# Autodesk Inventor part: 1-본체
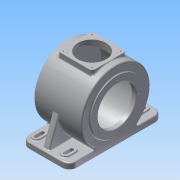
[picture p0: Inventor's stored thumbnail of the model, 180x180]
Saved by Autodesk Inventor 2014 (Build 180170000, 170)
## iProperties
Created: 2015-06
Part Number: 1-본체
Material: 알루미늄 6061
Document SubType Name: Modeling
Designer: Administrator
Density: 2.71 g/cm^3
Appearance: 알루미늄 - 평지
Mass: 3266.43 g
Surface Area: 2316.58 cm^2
Volume: 1205.33 cm^3
Author: Administrator
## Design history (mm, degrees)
sketch "스케치1"
  geometry: L1 (-67, 0)-(67, 0); L2 (-67, 0)-(-67, 65); L3 (-67, 65)-(-54, 65); L4 (-54, 65)-(-54, 85); L5 (-54, 85)-(64, 85); L6 (64, 85)-(64, 65); L7 (64, 65)-(67, 65); L8 (67, 65)-(67, 47.5); L9 (67, 47.5)-(56, 47.5); L10 (56, 47.5)-(56, 77); L11 (56, 77)-(-46, 77); L12 (-46, 77)-(-46, 31); L13 (-46, 31)-(-42.5, 29.368); L14 (-42.5, 29.368)-(-42.5, 23.5); L15 (-42.5, 23.5)-(-56.5, 23.5); L16 (-56.5, 23.5)-(-56.5, 15); L17 (-56.5, 15)-(-59.5, 15); L18 (-59.5, 15)-(-59.5, 0); 2 further points
  constraints: 36 end point, 11 parallel, 3 perpendicular, 1 coincident, 1 collinear, 1 horizontal, 1 midpoint, 1 point on line, 1 vertical, 1 vertical alignment
  dimensions: "d5" = 134 distance of L1.start L1.end; "d6" = 170 diameter of L5 L1; "d7" = 130 diameter of L3 L1; "d8" = 130 diameter of L7 L1; "d9" = 95 diameter of L9 L1; "d10" = 154 diameter of L11 L1; "d11" = 30 diameter of L17 L1; "d12" = 47 diameter of L15 L1; "d13" = 115 deg angle of L13 L12; "d14" = 62 diameter of L12.end L1; "d15" = 14 distance of L14.end L15.end; "d16" = 3 distance of L16.end L17.end; "d17" = 8 distance between parallel lines of L12 L4; "d18" = 8 distance between parallel lines of L6 L10; "d19" = 3.5 horizontal distance of L12.end L13.end; "d20" = 118 distance of L4.end L5.end; "d21" = 11 distance of L8.end L9.end
revolve "회전1" sketch "스케치1" stored, may be unused: angle "d22" = 90 deg
node "작업 평면1"
sketch "스케치2"
  geometry: L1 (46, -115)-(-36, -115); L2 (-54, -97)-(-54, 97); L3 (-36, 115)-(46, 115); L4 (64, 97)-(64, -97); L5 (64, -115)-(-54, 115); L6 (-54, -115)-(64, 115); L7 (-54, -85)-(-54, 85) reference; L8 (64, -85)-(64, 85) reference; L9 (-67, -65)-(-67, 65) reference; A1 r 18 centre (-36, -97) between (-54, -97) and (-36, -115); A2 r 18 centre (46, -97) between (46, -115) and (64, -97); A3 r 18 centre (46, 97) between (64, 97) and (46, 115); A4 r 18 centre (-36, 97) between (-36, 115) and (-54, 97); 3 further points
  constraints: 12 end point, 8 point on circle, 8 point on line, 8 tangent, 4 centre point, 4 midpoint, 3 equal radius, 2 collinear, 2 parallel, 1 horizontal, 1 horizontal alignment, 1 perpendicular
  dimensions: "d26" = 18 radius of A1; "d83" = 230 distance between parallel lines of L1 L3
extrude "돌출2" join sketch "스케치2" distance "d27" = 14; taper "d28" = 0 deg
node "작업 평면2"
sketch "스케치4"
  geometry: L1 (-37.5, 42.5)-(47.5, 42.5); L2 (47.5, 42.5)-(47.5, -42.5); L3 (47.5, -42.5)-(-37.5, -42.5); L4 (-37.5, -42.5)-(-37.5, 42.5); L5 (-37.5, 42.5)-(47.5, -42.5); L6 (47.5, 42.5)-(-37.5, -42.5); L7 (46, 115)-(-36, 115) reference; L8 (-67, -65)-(-67, 65) reference; 5 further points
  constraints: 12 end point, 6 midpoint, 2 parallel, 1 horizontal, 1 horizontal alignment, 1 perpendicular, 1 vertical, 1 vertical alignment
  dimensions: "d101" = 85 distance of L1.end L2.end
extrude "돌출3" join sketch "스케치4" stored distance "d41" = 14; taper "d42" = 0 deg
sketch "스케치7"
  geometry: L1 (64, -97)-(64, -46.733) reference; L2 (-45, -97)-(-45, -81); L3 (-27, -81)-(-27, -97); A1 r 18 centre (-36, -97) between (-54, -97) and (-36, -115) reference; A2 r 9 centre (-36, -81) between (-27, -81) and (-45, -81); A3 r 9 centre (-36, -97) between (-45, -97) and (-27, -97); 1 further point
  constraints: 4 end point, 4 point on circle, 4 tangent, 2 centre point, 2 parallel, 1 coincident
  dimensions: "d58" = 18 distance between parallel lines of L2 L3; "d59" = 16 distance of A2.centre A1.centre
extrude "돌출4" join sketch "스케치7" distance "d60" = 3; taper "d61" = 0 deg
sketch "스케치8"
  geometry: L1 (-45, -81)-(-45, -97) reference; L2 (-27, -97)-(-27, -81) reference; L3 (-40, -97)-(-40, -81); L4 (-32, -81)-(-32, -97); A1 r 9 centre (-36, -97) between (-45, -97) and (-27, -97) reference; A2 r 9 centre (-36, -81) between (-27, -81) and (-45, -81) reference; A3 r 4 centre (-36, -81) between (-32, -81) and (-40, -81); A4 r 4 centre (-36, -97) between (-40, -97) and (-32, -97); 1 further point
  constraints: 4 end point, 4 point on circle, 2 centre point, 3 other
  dimensions: "d62" = 8 distance between parallel lines of L3 L4
extrude "돌출5" cut sketch "스케치8" stored distance "d63" = 3; taper "d64" = 0 deg
sketch "스케치9"
  geometry: L1 (-97, -71)-(-115, -71) reference; L2 (115, -71)-(97, -71) reference; L3 (-109, -71)-(-84.87, -4.703); L4 (109, -71)-(84.87, -4.703); L5 (-115, -85)-(-115, -71) reference; L6 (115, -85)-(115, -71) reference; L7 (-109, -71)-(-46.733, -71); L8 (46.733, -71)-(109, -71); A1 r 85 centre (0, 0) between (-84.87, -4.703) and (84.87, -4.703) reference; 1 further point
  constraints: 8 end point, 4 point on circle, 4 point on line, 1 collinear
  dimensions: "d65" = 110 deg angle of L1 L3; "d66" = 6 distance from line of L3.start L5; "d67" = 110 deg angle of L2 L4; "d68" = 6 distance from line of L4.start L6
extrude "돌출6" join sketch "스케치9" stored distance "d69" = 15; taper "d70" = 0 deg
sketch "스케치10"
  geometry: L1 (29.799, -71)-(-29.799, -71) reference; A1 r 77 centre (0, 0) between (29.799, -71) and (-29.799, -71) reference; 2 further points
  constraints: 1 coincident, 3 other
extrude "돌출7" cut sketch "스케치10" stored distance "d71" = 102; taper "d72" = 0 deg
extrude "돌출8" cut sketch "스케치10" stored distance "d73" = 15; taper "d74" = 0 deg
sketch "스케치11"
  geometry: C1 r 65 at (0, 0) reference; C2 r 47.5 at (0, 0) reference; A1 r 55 centre (0, 0) between (-55, 0) and (0, -55); 2 further points
  constraints: 4 point on circle, 2 horizontal alignment, 2 vertical alignment, 1 centre point, 1 coincident
  dimensions: "d75" = 110 diameter of A1
hole "구멍3" sketch "스케치11" at (-55, 0), (0, -55), (0, 55), (55, 0) diameter "d76" = 3.242; stored, may be unused: countersink angle "d80" = 90 deg, drill point angle "d82" = 0 deg; dims "d77" = 10, "d78" = 4, "d79" = 2, "d81" = 13
fillet "모깎기1" dims "d84" = 3
fillet "모깎기2" dims "d85" = 3
fillet "모깎기3" dims "d86" = 3
fillet "모깎기4" dims "d87" = 3
fillet "모깎기5" dims "d88" = 3
fillet "모깎기6" dims "d89" = 3
node "작업 평면5"
  node "작업 평면4"
sketch "스케치12"
  geometry: 2 further points
  constraints: 1 coincident, 1 other
feature "엠보싱1" sketch "스케치12" dims "d5" = 134, "d92" = 1, "d93" = 0
fillet "모깎기7" dims "d94" = 3
fillet "모깎기8" dims "d95" = 0.3
fillet "모깎기9" dims "d96" = 3
chamfer "모따기1" distance "d97" = 1; stored, may be unused: second distance "d98" = 2, angle "d99" = 45 deg
fillet "모깎기10" dims "d100" = 7
sketch "스케치13"
  geometry: L1 (-30.5, 42.5)-(40.5, 42.5) reference; L2 (-30.5, -35.5)-(40.5, -35.5); L3 (40.5, -35.5)-(40.5, 35.5); L4 (40.5, 35.5)-(-30.5, 35.5); L5 (-30.5, 35.5)-(-30.5, -35.5); L6 (-30.5, -35.5)-(40.5, 35.5); L7 (40.5, -35.5)-(-30.5, 35.5); 7 further points
  constraints: 12 end point, 4 coincident, 3 midpoint, 2 parallel, 2 perpendicular, 1 horizontal, 1 horizontal alignment, 1 vertical alignment
  dimensions: "d103" = 71 distance of L2.end L3.end
hole "구멍4" sketch "스케치13" at (5, 0), (-30.5, 35.5), (40.5, 35.5), (40.5, -35.5), (-30.5, -35.5) diameter "d104" = 2.459; stored, may be unused: countersink angle "d108" = 90 deg, drill point angle "d110" = 118 deg; dims "d105" = 10, "d106" = 4, "d107" = 2, "d109" = 13
hole "구멍5" sketch "스케치4" diameter "d111" = 70; stored, may be unused: countersink angle "d115" = 90 deg, drill point angle "d117" = 118 deg; dims "d112" = 10, "d113" = 4, "d114" = 2, "d116" = 13
node "솔리드2"
mirror "대칭1"
mirror "대칭2"
node "작업 평면3"
other parameters: "d23" = -85, "d39" = 86.5, "d90" = -65 deg, "d91" = 0.5
